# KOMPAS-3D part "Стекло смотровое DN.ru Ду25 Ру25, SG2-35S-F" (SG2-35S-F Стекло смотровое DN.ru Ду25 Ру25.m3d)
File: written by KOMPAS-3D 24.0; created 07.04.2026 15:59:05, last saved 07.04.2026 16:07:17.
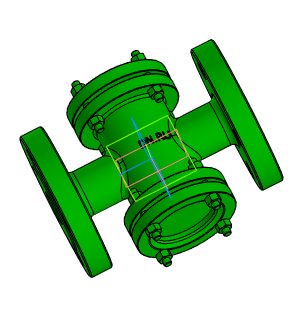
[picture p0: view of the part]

Document properties: Автор: Main; Полное имя файла: D:\DN.ru Аутсерс\Стекло смотровое DN.ru\SG2-35S-F Стекло смотровое DN.ru Ду25 Ру25\SG2-35S-F Стекло смотровое DN.ru Ду25 Ру25.m3d

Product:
- Body: Тело 1  | qty 1
    Масса: 4.394636
- Part/product: Стекло смотровое DN.ru Ду25 Ру25  | designation SG2-35S-F
    Масса: 5.5
    Раздел спецификации: Прочие изделия
    Примечание: D500-00093

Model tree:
1. Операция без истории:1

Expressions: SG2-35S-F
